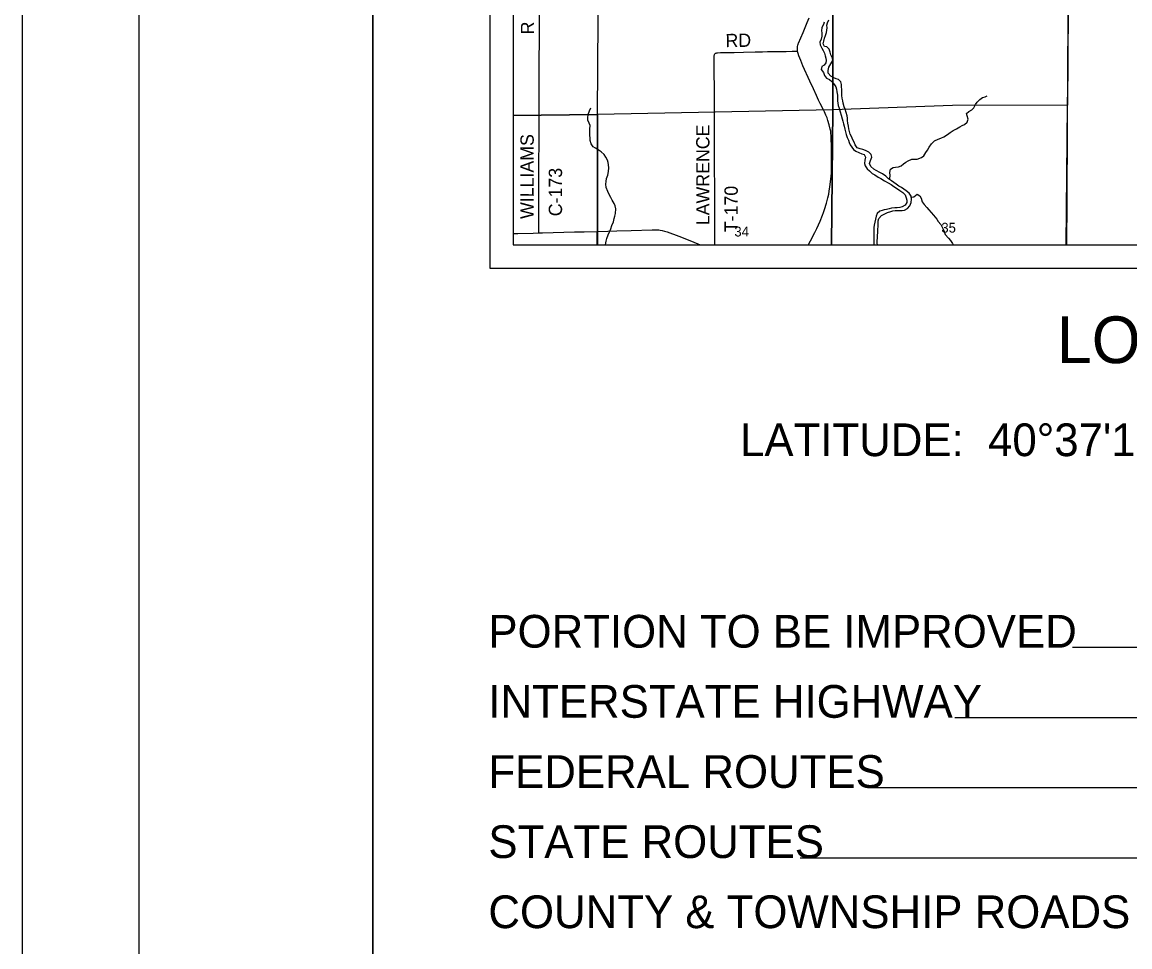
# Model space of a CAD drawing. Extents: x 0 to 45.9, y 0 to 22.
# Drawn here: x 0 to 4.739, y 11.097 to 15.053 of the extents above; entities that cross this region are included whole.
import ezdxf

# ---------------------------------------------------------------- set-up
doc = ezdxf.new("R2010")
doc.units = 0
for name, color, linetype in [('Default', 7, 'Continuous'), ('GM_X_County_Road', 7, 'Continuous'), ('GM_X_County_Road_Text', 7, 'Continuous'), ('GM_X_Major_River', 7, 'Continuous'), ('GM_X_Minor_River', 7, 'Continuous'), ('GM_X_Section', 7, 'Continuous'), ('GM_X_Section_Text', 7, 'Continuous'), ('GM_X_Township_Road', 7, 'Continuous'), ('GM_X_Township_Road_Text', 7, 'Continuous'), ('SH_Border', 7, 'Continuous'), ('SH_Cut_Line', 7, 'Continuous'), ('SH_Data', 7, 'Continuous'), ('SH_Text', 7, 'Continuous')]:
    doc.layers.add(name, color=color, linetype=linetype)

msp = doc.modelspace()

# ---------------------------------------------------------------- linework, layer by layer
at = {"layer": 'Default'}
for points in [[(2.1, 19.7114), (2.1, 14.1), (5.4538, 14.1), (5.4606, 15.6588), (5.4651, 16.7018), (5.4694, 17.7061), (5.4802, 18.3214), (5.4737, 18.7216), (5.4752, 19.0482), (5.4759, 19.2109), (5.4773, 19.7108), (5.0826, 19.712), (3.7367, 19.7072), (2.15, 19.7113)], [(2.1, 15.6753), (2.1, 14.6532), (2.4618, 14.6575), (2.4689, 15.6797)], [(3.4628, 14.1), (4.4668, 14.1), (4.4719, 14.697), (3.9797, 14.6959), (3.4686, 14.6772)], [(2.1, 14.6532), (2.1, 14.1), (2.4617, 14.1), (2.4618, 14.6575)], [(2.4617, 14.1), (3.4628, 14.1), (3.4686, 14.6772), (2.4618, 14.6575)]]:
    msp.add_lwpolyline(points, close=True, dxfattribs=at)
at = {"layer": 'GM_X_County_Road'}
for points in [[(2.2097, 14.1508), (2.2097, 14.1571), (2.2097, 14.1945), (2.21, 14.2349), (2.2104, 14.2939), (2.2105, 14.3685), (2.2108, 14.468), (2.211, 14.5224), (2.211, 14.5395), (2.2111, 14.5706), (2.2113, 14.6141), (2.2115, 14.67), (2.2117, 14.7105), (2.2117, 14.7509), (2.2119, 14.8099), (2.2123, 14.9063), (2.2125, 14.9591), (2.2127, 15.0431), (2.2129, 15.0928), (2.2132, 15.155), (2.2133, 15.2482), (2.2138, 15.3477), (2.214, 15.4036), (2.214, 15.4101)], [(3.3171, 14.9291), (3.3165, 14.9329), (3.3163, 14.9359), (3.3164, 14.9384), (3.3166, 14.9412), (3.3175, 14.9481), (3.3186, 14.9542), (3.3197, 14.9584), (3.3202, 14.96), (3.3211, 14.963), (3.3404, 15.0087), (3.3585, 15.0517), (3.367, 15.0716)], [(4.4694, 14.1), (4.4696, 14.1288), (4.4696, 14.1723), (4.47, 14.2158), (4.4706, 14.3308), (4.4707, 14.4147), (4.4711, 14.4706), (4.4712, 14.5514), (4.4716, 14.6167), (4.4722, 14.6944), (4.4726, 14.7721), (4.4732, 14.8343), (4.4739, 14.9213), (4.4746, 14.9803), (4.475, 15.0359), (4.4752, 15.1016)], [(3.3638, 14.1), (3.3642, 14.1008), (3.3724, 14.1176), (3.3913, 14.1533), (3.3995, 14.1701), (3.4133, 14.2013), (3.4242, 14.2271), (3.4287, 14.2388), (3.4325, 14.2506), (3.4404, 14.2775), (3.4468, 14.3016), (3.4503, 14.3167), (3.4527, 14.329), (3.4555, 14.3474), (3.4581, 14.3691), (3.4617, 14.4062), (3.4624, 14.4185), (3.4626, 14.4279), (3.4628, 14.4403), (3.4629, 14.4527), (3.4627, 14.4683), (3.4624, 14.4807), (3.4618, 14.5241), (3.4614, 14.5521), (3.4608, 14.5676), (3.46, 14.5769), (3.4588, 14.5862), (3.457, 14.5954), (3.4523, 14.6135), (3.4471, 14.6314), (3.4431, 14.6432), (3.4386, 14.6548), (3.4323, 14.6691), (3.4267, 14.6802), (3.4141, 14.7051), (3.4071, 14.719), (3.3977, 14.7386), (3.3847, 14.7668), (3.3693, 14.8007), (3.3401, 14.866), (3.3304, 14.8889), (3.3226, 14.9091), (3.3197, 14.9179), (3.3175, 14.9269), (3.3171, 14.9291)], [(2.1, 14.1484), (2.121, 14.1489), (2.1862, 14.1502), (2.2097, 14.1508)], [(2.2097, 14.1508), (2.2266, 14.1512), (2.3167, 14.1537), (2.3632, 14.1549), (2.4036, 14.1555), (2.4593, 14.1572)], [(2.4593, 14.1572), (2.5061, 14.1585), (2.5434, 14.1596), (2.6055, 14.1616), (2.6955, 14.1643), (2.7141, 14.1645), (2.7233, 14.164), (2.7294, 14.1633), (2.7385, 14.1614), (2.7474, 14.159), (2.7592, 14.155), (2.8087, 14.1366), (2.8637, 14.1152), (2.901, 14.1)]]:
    msp.add_lwpolyline(points, dxfattribs=at)
at = {"layer": 'GM_X_Major_River'}
for points in [[(3.4315, 15.0526), (3.428, 15.0424), (3.421, 15.0292), (3.42, 15.016), (3.421, 15.0065), (3.4208, 14.9924), (3.418, 14.9803), (3.4129, 14.9671), (3.4131, 14.955), (3.4213, 14.9408), (3.4265, 14.9313), (3.4324, 14.9198), (3.4353, 14.9084), (3.4378, 14.8985), (3.4392, 14.8882), (3.4383, 14.8784), (3.4313, 14.8682), (3.421, 14.8623), (3.4185, 14.8498), (3.4279, 14.8375), (3.4319, 14.8242), (3.4404, 14.8131), (3.4536, 14.8068), (3.4634, 14.7987), (3.4746, 14.7849), (3.4801, 14.7754), (3.483, 14.7655), (3.4852, 14.7548), (3.488, 14.74), (3.4886, 14.7301), (3.4884, 14.7157), (3.4898, 14.7054), (3.4912, 14.6959), (3.4949, 14.6845), (3.4996, 14.6689), (3.5039, 14.6544), (3.5075, 14.6396), (3.5104, 14.6285), (3.5137, 14.6175), (3.5158, 14.6072), (3.5187, 14.5954), (3.5219, 14.5836), (3.5252, 14.5722), (3.5296, 14.5592), (3.5344, 14.5478), (3.5384, 14.5375), (3.5421, 14.5279), (3.5491, 14.5176), (3.5558, 14.508), (3.5664, 14.5007), (3.5788, 14.4944), (3.5924, 14.4897), (3.6026, 14.4861), (3.6081, 14.4754), (3.6042, 14.4618), (3.6032, 14.4478), (3.6057, 14.4375), (3.6147, 14.4253), (3.6244, 14.4168), (3.6368, 14.4056), (3.6481, 14.399), (3.6613, 14.3901), (3.6737, 14.3831), (3.6891, 14.3742), (3.7053, 14.3656), (3.7173, 14.3575), (3.7283, 14.3501), (3.7403, 14.342), (3.7542, 14.3327), (3.7674, 14.3234), (3.7771, 14.3134), (3.7822, 14.3016), (3.7851, 14.2913), (3.7842, 14.2815), (3.7769, 14.269), (3.7643, 14.2624), (3.754, 14.2595), (3.743, 14.2585)], [(3.4719, 14.8138), (3.4588, 14.8212), (3.4483, 14.8346), (3.4477, 14.846), (3.4509, 14.8596), (3.4598, 14.8739), (3.4684, 14.8886), (3.4663, 14.8992), (3.46, 14.913), (3.456, 14.9237), (3.4523, 14.937), (3.4426, 14.9477), (3.4324, 14.9486), (3.4269, 14.9601), (3.4293, 14.9714), (3.4325, 14.9835), (3.4364, 14.9956), (3.4408, 15.0077), (3.4428, 15.0183), (3.4433, 15.0289), (3.4427, 15.0392), (3.4448, 15.0494), (3.451, 15.0626)], [(3.6587, 14.1), (3.6582, 14.1071), (3.658, 14.1174), (3.6585, 14.1295), (3.659, 14.1394), (3.66, 14.153), (3.6609, 14.1674), (3.6614, 14.1784), (3.6612, 14.1917), (3.6618, 14.2031), (3.6649, 14.2133), (3.6761, 14.2249), (3.6872, 14.2308), (3.7021, 14.2378), (3.7154, 14.2426), (3.7253, 14.2451), (3.7352, 14.2468), (3.764, 14.2464), (3.7743, 14.2478), (3.7869, 14.2549), (3.7973, 14.2669), (3.8028, 14.2816), (3.8049, 14.2956), (3.8032, 14.3085), (3.7946, 14.3215), (3.7811, 14.3316), (3.7713, 14.3382), (3.7612, 14.3448), (3.7506, 14.3506), (3.739, 14.3591), (3.7289, 14.3664), (3.7187, 14.3738), (3.7063, 14.3827), (3.6943, 14.3938), (3.6804, 14.4031), (3.6695, 14.4097), (3.654, 14.4179), (3.6431, 14.4241), (3.6304, 14.4349), (3.6248, 14.4483), (3.6296, 14.4611), (3.6343, 14.4755), (3.6326, 14.4857), (3.6213, 14.4969), (3.607, 14.5035), (3.5968, 14.5075), (3.5851, 14.5103), (3.5719, 14.515), (3.5633, 14.5273), (3.5589, 14.5387), (3.5541, 14.5494), (3.5475, 14.5631), (3.5427, 14.5738), (3.5394, 14.5845), (3.5365, 14.5963), (3.5344, 14.6073), (3.5327, 14.6199), (3.5313, 14.6324), (3.5307, 14.6423), (3.5297, 14.6522), (3.5253, 14.6659), (3.5202, 14.68), (3.5162, 14.6907), (3.5122, 14.7055), (3.5101, 14.7165), (3.5076, 14.7276), (3.5066, 14.7382), (3.506, 14.7519), (3.5058, 14.764), (3.5056, 14.7754), (3.5046, 14.7857), (3.5021, 14.7967), (3.4919, 14.8067), (3.4821, 14.8106), (3.4719, 14.8138)], [(3.743, 14.2585), (3.7331, 14.2579), (3.719, 14.2565), (3.7095, 14.2544), (3.6973, 14.2511), (3.6878, 14.249), (3.6783, 14.2468), (3.6684, 14.2439), (3.6569, 14.2335), (3.6529, 14.2225), (3.6501, 14.2104), (3.6469, 14.1972), (3.6448, 14.1847), (3.6439, 14.1748), (3.6434, 14.1619), (3.6436, 14.1502), (3.6438, 14.1396), (3.6435, 14.1172), (3.643, 14.1073), (3.6429, 14.1)]]:
    msp.add_lwpolyline(points, dxfattribs=at)
at = {"layer": 'GM_X_Minor_River'}
for points in [[(3.7103, 14.3798), (3.712, 14.3837), (3.7133, 14.3966), (3.7112, 14.4095), (3.7141, 14.4239), (3.7255, 14.431), (3.7366, 14.4316), (3.7483, 14.433), (3.7605, 14.4381), (3.7705, 14.4459), (3.7805, 14.4534), (3.7908, 14.4597), (3.8053, 14.4667), (3.8156, 14.4662), (3.8292, 14.4664), (3.8468, 14.4734), (3.8567, 14.4801), (3.8664, 14.4947), (3.8726, 14.5053), (3.88, 14.5181), (3.8901, 14.5327), (3.9031, 14.5443), (3.9184, 14.5521), (3.9302, 14.5557), (3.9432, 14.5624), (3.9581, 14.572), (3.97, 14.5802), (3.9826, 14.5888), (3.9964, 14.5969), (4.0109, 14.6051), (4.0213, 14.6103), (4.0308, 14.6147), (4.0423, 14.6244), (4.0463, 14.6376), (4.0431, 14.6513), (4.0398, 14.6624), (4.0498, 14.6702), (4.0631, 14.6768), (4.0716, 14.6866), (4.0786, 14.6998), (4.0848, 14.7103), (4.0964, 14.7223), (4.1086, 14.7301), (4.1189, 14.7334), (4.1288, 14.7367)], [(2.4955, 14.1), (2.4987, 14.1156), (2.5017, 14.1274), (2.5075, 14.1429), (2.5125, 14.155), (2.5178, 14.1679), (2.5232, 14.1826), (2.5293, 14.1982), (2.5328, 14.2129), (2.5355, 14.2231), (2.5381, 14.2345), (2.5401, 14.2535), (2.5367, 14.2664), (2.5322, 14.277), (2.524, 14.2907), (2.5179, 14.3028), (2.5108, 14.3157), (2.5048, 14.3275), (2.4984, 14.3457), (2.4973, 14.3601), (2.4977, 14.3704), (2.5004, 14.3836), (2.505, 14.398), (2.5081, 14.4132), (2.5093, 14.4295), (2.5086, 14.4416), (2.5067, 14.4522), (2.5034, 14.4621), (2.497, 14.475), (2.4902, 14.486), (2.4773, 14.4978), (2.4645, 14.5062), (2.452, 14.5131), (2.4422, 14.5195), (2.4343, 14.5321), (2.4305, 14.5461), (2.4298, 14.5567), (2.4291, 14.5693), (2.428, 14.5787), (2.4288, 14.5943), (2.43, 14.6098), (2.4259, 14.6208), (2.4195, 14.6337), (2.4195, 14.6432), (2.4215, 14.658), (2.4265, 14.6727), (2.4329, 14.686)], [(3.8039, 14.3034), (3.8138, 14.3057), (3.828, 14.3165), (3.84, 14.3095), (3.8456, 14.2996), (3.8507, 14.2844), (3.8593, 14.2732), (3.8697, 14.2594), (3.8779, 14.2498), (3.8884, 14.2379), (3.8985, 14.2264), (3.9127, 14.2095), (3.9186, 14.2), (3.9294, 14.1873), (3.9387, 14.1705), (3.9442, 14.1575), (3.9478, 14.1438), (3.9624, 14.1284), (3.971, 14.1185), (3.9792, 14.1051), (3.9831, 14.1)]]:
    msp.add_lwpolyline(points, dxfattribs=at)
at = {"layer": 'GM_X_Section'}
for points in [[(3.467, 15.6926), (3.4686, 14.6772), (2.4618, 14.6575), (2.4689, 15.6797)], [(4.4787, 15.7127), (4.4719, 14.697), (3.9797, 14.6959), (3.4686, 14.6772), (3.467, 15.6926)]]:
    msp.add_lwpolyline(points, close=True, dxfattribs=at)
at = {"layer": 'GM_X_Township_Road'}
for points in [[(2.9631, 14.1), (2.9631, 14.1001), (2.963, 14.1224), (2.9629, 14.153), (2.9628, 14.2059), (2.9626, 14.2433), (2.9625, 14.3179), (2.9625, 14.3584), (2.9624, 14.4175), (2.9623, 14.4548), (2.9621, 14.4953), (2.9619, 14.5128), (2.9617, 14.5419), (2.9614, 14.5793), (2.9616, 14.6291), (2.9614, 14.6602), (2.9617, 14.7069), (2.9614, 14.738), (2.9611, 14.7858), (2.9609, 14.8221), (2.9605, 14.8624), (2.96, 14.8935), (2.9601, 14.9029), (2.9602, 14.9084), (2.9606, 14.9105), (2.9611, 14.9126), (2.9619, 14.9147), (2.9629, 14.9167), (2.9645, 14.9181), (2.9664, 14.9194), (2.9687, 14.9204), (2.9713, 14.9212), (2.9743, 14.9216), (2.9867, 14.9221), (3.0457, 14.9233), (3.086, 14.9238), (3.1356, 14.925), (3.1666, 14.9257), (3.1883, 14.9264), (3.2131, 14.9268), (3.2441, 14.9272), (3.2689, 14.9277), (3.2937, 14.9281), (3.3092, 14.9288), (3.3171, 14.9291)], [(2.4595, 14.1), (2.4595, 14.1095), (2.4594, 14.1498), (2.4593, 14.1572)]]:
    msp.add_lwpolyline(points, dxfattribs=at)
at = {"layer": 'SH_Cut_Line'}
for p, q in [((2, 21), (2, 14)), ((2.1, 20.9), (2.1, 14.1)), ((2.1, 14.1), (8.9, 14.1)), ((2.1, 14.1), (2.1, 14.1)), ((2, 14), (9, 14)), ((7.7, 12.3767), (4.4937, 12.3767)), ((7.7, 12.0767), (3.9895, 12.0767)), ((7.7, 11.7767), (3.6192, 11.7767)), ((7.7, 11.4767), (3.3288, 11.4767))]:
    msp.add_line(p, q, dxfattribs=at)
at = {"layer": 'SH_Data'}
for points in [[(0.5, 21.5), (1.5, 21.5), (1.5, 0.5), (0.5, 0.5)], [(1.5, 21.5), (33.5, 21.5), (33.5, 0.5), (1.5, 0.5)]]:
    msp.add_lwpolyline(points, close=True, dxfattribs=at)
at = {"layer": 'SH_Text'}
msp.add_lwpolyline([(0, 0), (34, 0), (34, 22), (0, 22)], close=True, dxfattribs=at)
msp.add_lwpolyline([(2.1, 20.9), (2.1, 14.1), (5.4538, 14.1), (5.4606, 15.6588)], dxfattribs=at)

# ---------------------------------------------------------------- texts
at = {"layer": 'GM_X_County_Road_Text'}
for s, height, rotation, p in [('R', 0.0568, 89.9961, (2.1902, 15.0005)), ('WILLIAMS', 0.05682, 89.863, (2.1877, 14.2105)), ('C-173', 0.05682, 90, (2.3096, 14.2222))]:
    msp.add_text(s, height=height, rotation=rotation, dxfattribs=at).set_placement(p)
at = {"layer": 'GM_X_Section_Text'}
for s, p in [('34', (3.0467, 14.1356)), ('35', (3.9321, 14.1523))]:
    msp.add_text(s, height=0.04186, rotation=0, dxfattribs=at).set_placement(p)
at = {"layer": 'GM_X_Township_Road_Text'}
for s, rotation, p in [('RD', 0.9747, (3.0091, 14.9454)), ('LAWRENCE', 90, (2.9402, 14.1839)), ('T-170', 90, (3.0612, 14.1539))]:
    msp.add_text(s, height=0.05682, rotation=rotation, dxfattribs=at).set_placement(p)
at = {"layer": 'SH_Border'}
for s, height, p in [('LOCATION MAP', 0.2, (4.4269, 13.5938)), ('LATITUDE:  40°37\'15"     LONGITUDE:  82°57\'45"', 0.14, (3.071, 13.1959)), ('PORTION TO BE IMPROVED', 0.14, (1.9944, 12.3767)), ('INTERSTATE HIGHWAY', 0.14, (1.9944, 12.0767)), ('FEDERAL ROUTES', 0.14, (1.9944, 11.7767)), ('STATE ROUTES', 0.14, (1.9944, 11.4767)), ('COUNTY & TOWNSHIP ROADS', 0.14, (1.9944, 11.1767))]:
    msp.add_text(s, height=height, dxfattribs=at).set_placement(p)

doc.saveas('drawing.dxf')
